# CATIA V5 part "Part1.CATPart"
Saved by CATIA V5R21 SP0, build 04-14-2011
Part number: Part1
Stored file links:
  F:\catia world\MY WORK\rack and pinion\Part1.CATPart

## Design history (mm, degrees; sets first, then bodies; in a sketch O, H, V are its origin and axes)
Body1 (main body)
  DatumSurface1
  DatumCurve1
  DatumSurface2
  Sketch1 on face of DatumSurface1, origin (0, 0, 206.5315), H (1, 0, 0), V (0, 1, 0)
    circle A1 centre (-212.5419, -34.856) radius 7.5
    reference projected arc E1 centre (-212.5419, -34.856) radius 7.5 from (-219.3872, -37.9207) to (-205.6967, -31.7913) ccw from edge of DatumCurve1
    coincidence: A1 E1
  Pad1: profile Sketch1, direction (0, 0, 1), length 55
  DatumCurve2
  Sketch2 on face of DatumSurface2, origin (0, 0, 206.5315), H (1, 0, 0), V (0, 1, 0)
    line L1 (-332.6791, -90.6452) -> (-138.9116, -90.6452)
    reference projected line E1 (-154.3155, -90.6452) -> (-150.0091, -90.6452) from edge of DatumCurve2
    horizontal: L1 H
    coincidence: L1 E1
